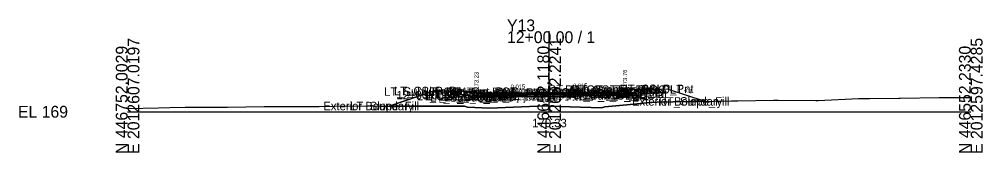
# Model space of a CAD drawing. Extents: x -26 to 1403, y -10 to 4517.
# Drawn here: x -25.7 to 202.8, y 3990.3 to 4021.9 of the extents above; entities that cross this region are included whole.
import ezdxf

# ---------------------------------------------------------------- set-up
doc = ezdxf.new("R2010")
doc.units = 0
for name, color, linetype in [('Default', 7, 'Continuous'), ('Exist Cross Section Cell', 7, 'Continuous'), ('Exist XS Center Line Elevation Label', 7, 'Continuous'), ('Exist XS Ground Line', 7, 'Continuous'), ('Prop CMT Conc Surface', 7, 'Continuous'), ('Prop CMT Concrete Structures', 7, 'Continuous'), ('Prop CMT Pvmt Course 1', 7, 'Continuous'), ('Prop CMT Pvmt Course 1 CG', 7, 'Continuous'), ('Prop CMT Pvmt Course 2', 7, 'Continuous'), ('Prop CMT Pvmt Course 3', 7, 'Continuous'), ('Prop CMT Pvmt Surface', 7, 'Continuous'), ('Prop CMT Slope Grass', 7, 'Continuous'), ('Prop CMT Subgrade Earthwork', 7, 'Continuous'), ('Prop XS Earthwork Shape', 7, 'Continuous'), ('Prop XS Hydro Elevations', 7, 'Continuous'), ('Prop XS SE Text', 7, 'Continuous'), ('Prop XS Side Slope Text', 7, 'Continuous'), ('Scratch_Level_0', 7, 'Continuous')]:
    doc.layers.add(name, color=color, linetype=linetype)

msp = doc.modelspace()

# ---------------------------------------------------------------- linework, layer by layer
at = {"layer": 'Exist Cross Section Cell'}
for p, q in [((100, 4000), (100, 4019.05)), ((0, 4000), (100, 4000)), ((100, 4000), (200, 4000))]:
    msp.add_line(p, q, dxfattribs=at)
at = {"layer": 'Exist XS Ground Line'}
msp.add_lwpolyline([(0, 4000.79), (7.31, 4000.95), (9.99, 4001.02), (13.63, 4001.09), (22.66, 4001.07), (23.71, 4001.07), (32.37, 4001.23), (40.65, 4001.21), (45.43, 4001.23), (52.89, 4001.42), (59.88, 4001.35), (72.72, 4001.32), (79.95, 4001.3), (80.65, 4001.12), (85.84, 4000.87), (99.11, 4001.38), (100, 4001.33), (112.41, 4000.89), (113.18, 4001.18), (118.45, 4001.64), (123.2, 4002.15), (125.62, 4002.24), (133.21, 4002.44), (135.17, 4002.45), (143.22, 4002.58), (144.72, 4002.58), (153.24, 4002.72), (154.28, 4002.72), (163.25, 4002.67), (163.83, 4002.7), (173.39, 4003.13), (175.98, 4003.16), (182.94, 4003.23), (183.27, 4003.24), (192.49, 4003.41), (193.29, 4003.41), (200, 4003.36)], dxfattribs=at)
at = {"layer": 'Prop CMT Conc Surface'}
for points in [[(82.75, 4004.23), (82.75, 4004.73), (82.25, 4004.73)], [(84.75, 4004.34), (82.75, 4004.23)], [(115.99, 4004.81), (117.99, 4004.76)], [(117.99, 4004.76), (118, 4005.26), (118.5, 4005.26)]]:
    msp.add_lwpolyline(points, dxfattribs=at)
at = {"layer": 'Prop CMT Concrete Structures'}
for points in [[(84.75, 4004.34), (82.75, 4004.23), (82.75, 4004.73), (82.25, 4004.73)], [(82.25, 4004.73), (82.25, 4003.72), (84.75, 4003.76)], [(84.75, 4003.76), (84.75, 4004.34)], [(115.99, 4004.81), (117.99, 4004.76), (118, 4005.26), (118.5, 4005.26)], [(118.5, 4005.26), (118.49, 4004.26), (115.99, 4004.23)], [(115.99, 4004.23), (115.99, 4004.81)]]:
    msp.add_lwpolyline(points, dxfattribs=at)
at = {"layer": 'Prop CMT Pvmt Course 1'}
for points in [[(100, 4004.57), (84.75, 4004.34)], [(84.75, 4004.34), (84.75, 4004.09)], [(84.75, 4004.09), (100, 4004.32)], [(100, 4004.57), (115.99, 4004.81)], [(100, 4004.32), (100, 4004.57)], [(100, 4004.32), (100, 4004.57)], [(115.99, 4004.56), (100, 4004.32)], [(115.99, 4004.81), (115.99, 4004.56)]]:
    msp.add_lwpolyline(points, dxfattribs=at)
msp.add_lwpolyline([(100, 4004.32), (100, 4004.44), (100, 4004.44), (100, 4004.32)], close=True, dxfattribs=at)
msp.add_lwpolyline([(100, 4004.32), (100, 4004.44), (100, 4004.44), (100, 4004.32)], close=True, dxfattribs=at)
at = {"layer": 'Prop CMT Pvmt Course 1 CG'}
for points in [[(115.99, 4004.23), (118.99, 4004.27), (119.32, 4003.94)], [(115.99, 4003.89), (115.99, 4004.23)], [(119.32, 4003.94), (115.99, 4003.89)], [(84.75, 4003.76), (81.75, 4003.71), (81.41, 4003.37)], [(81.41, 4003.37), (84.75, 4003.42)], [(84.75, 4003.42), (84.75, 4003.76)]]:
    msp.add_lwpolyline(points, dxfattribs=at)
at = {"layer": 'Prop CMT Pvmt Course 2'}
for points in [[(100, 4004.32), (84.75, 4004.09)], [(84.75, 4004.09), (84.75, 4003.76)], [(84.75, 4003.76), (100, 4003.99)], [(100, 4004.32), (115.99, 4004.56)], [(100, 4003.99), (100, 4004.32)], [(100, 4003.99), (100, 4004.32)], [(115.99, 4004.23), (100, 4003.99)], [(115.99, 4004.56), (115.99, 4004.23)]]:
    msp.add_lwpolyline(points, dxfattribs=at)
at = {"layer": 'Prop CMT Pvmt Course 3'}
for points in [[(100, 4003.99), (84.75, 4003.76)], [(100, 4003.99), (115.99, 4004.23)], [(100, 4003.65), (100, 4003.99)], [(100, 4003.65), (100, 4003.99)], [(115.99, 4003.89), (100, 4003.65)], [(115.99, 4004.23), (115.99, 4003.89)], [(84.75, 4003.76), (84.75, 4003.42)], [(84.75, 4003.42), (100, 4003.65)]]:
    msp.add_lwpolyline(points, dxfattribs=at)
at = {"layer": 'Prop CMT Pvmt Surface'}
for points in [[(100, 4004.57), (84.75, 4004.34)], [(100, 4004.57), (115.99, 4004.81)]]:
    msp.add_lwpolyline(points, dxfattribs=at)
at = {"layer": 'Prop CMT Slope Grass'}
for points in [[(82.25, 4004.73), (72.75, 4004.92), (62.03, 4001.35)], [(118.5, 4005.26), (128, 4005.45), (136.92, 4002.48)]]:
    msp.add_lwpolyline(points, dxfattribs=at)
at = {"layer": 'Prop CMT Subgrade Earthwork'}
for points in [[(84.75, 4003.42), (81.41, 4003.37), (80.01, 4004.77)], [(100, 4003.65), (115.99, 4003.89)], [(115.99, 4003.89), (119.32, 4003.94), (120.68, 4005.3)], [(100, 4003.65), (84.75, 4003.42)]]:
    msp.add_lwpolyline(points, dxfattribs=at)
at = {"layer": 'Prop XS Earthwork Shape'}
msp.add_lwpolyline([(115.99, 4003.89), (119.32, 4003.94), (120.68, 4005.3), (128, 4005.45), (136.92, 4002.48), (135.17, 4002.45), (133.21, 4002.44), (125.62, 4002.24), (123.2, 4002.15), (118.45, 4001.64), (113.18, 4001.18), (112.41, 4000.89), (100, 4001.33), (99.11, 4001.38), (85.84, 4000.87), (80.65, 4001.12), (79.95, 4001.3), (72.72, 4001.32), (62.03, 4001.35), (72.75, 4004.92), (80.01, 4004.77), (81.41, 4003.37), (84.75, 4003.42), (100, 4003.65)], close=True, dxfattribs=at)

# ---------------------------------------------------------------- texts
at = {"layer": 'Default'}
msp.add_text('-', height=0.0001, dxfattribs=at).set_placement((0, 4000))
at = {"layer": 'Exist Cross Section Cell'}
for s, p in [('Y13', (90, 4019.05)), ('12+00.00 / 1', (90, 4016.25)), ('EL 169', (-26, 3998.6))]:
    msp.add_text(s, height=2.8, dxfattribs=at).set_placement(p)
for s, p in [('N 446752.0029', (0, 3990)), ('E 2012607.0197', (2.8, 3990)), ('N 446652.1180', (100, 3990)), ('E 2012602.2241', (102.8, 3990)), ('N 446552.2330', (200, 3990)), ('E 2012597.4285', (202.8, 3990))]:
    msp.add_text(s, height=2.8, rotation=90, dxfattribs=at).set_placement(p)
at = {"layer": 'Exist XS Center Line Elevation Label'}
msp.add_text('170.33', height=2, dxfattribs=at).set_placement((95.99, 3996.33))
at = {"layer": 'Prop XS Hydro Elevations'}
for s, p in [('173.23', (83.25, 4005.23)), ('173.76', (118.49, 4005.76))]:
    msp.add_text(s, height=1, rotation=90, dxfattribs=at).set_placement(p)
at = {"layer": 'Prop XS SE Text'}
for p in [(90.88, 4005.43), (105.66, 4005.65)]:
    msp.add_text('0.015', height=1, rotation=0.8594, dxfattribs=at).set_placement(p)
at = {"layer": 'Prop XS Side Slope Text'}
for rotation, p in [(18.4332, (66.39, 4003.59)), (341.5668, (131.95, 4004.92))]:
    msp.add_text('3:1', height=1, rotation=rotation, dxfattribs=at).set_placement(p)
at = {"layer": 'Scratch_Level_0'}
for s, p in [('RT_Sub_Trench_Out_DLT', (99.79, 4004.28)), ('RT_CG_Top_Face', (103.79, 4004.24)), ('RT_CG_Top_BOC', (105.31, 4004.24)), ('RT_CSLP_Pnt', (116.7, 4004.43)), ('LT_Sub_Trench_Out_DLT', (60.84, 4003.78)), ('LT_CSLP_Pnt', (63.18, 4003.92)), ('12+00.00', (63.8, 4002.94)), ('LT_CG1_Shelf_Out', (68.56, 4002.72)), ('LT_CG_Top_Face', (70.27, 4003.73)), ('LT_CG_Top_BOC', (70.79, 4003.73)), ('LT_CG_Bot_BOC', (70.83, 4002.72)), ('LT_CG_Top_Gut', (71.25, 4003.23)), ('LT_Sub_OEOP', (71.78, 4002.38)), ('LT_CG_Bot_IE', (74.92, 4002.76)), ('LT_Sub_OEOT', (75.09, 4002.43)), ('LT_PV2_OEOT', (75.18, 4003.09)), ('LT_PV3_OEOT', (75.18, 4002.76)), ('LT_PV1_OEOT', (75.75, 4003.34)), ('RT_Sub_OEEOP', (89.17, 4002.65)), ('LT_Sub_OEEOP', (89.21, 4002.65)), ('RT_PV2_OEEOP', (89.26, 4003.32)), ('RT_PV3_OEEOP', (89.26, 4002.99)), ('LT_PV2_OEEOP', (89.31, 4003.32)), ('LT_PV3_OEEOP', (89.31, 4002.99)), ('RT_PV1_OEEOP', (89.83, 4003.44)), ('LT_PV1_OEEOP', (89.87, 4003.44)), ('RT_PV2_IEEOP', (89.91, 4003.32)), ('LT_PV2_IEEOP', (89.95, 4003.32)), ('RT_PV1_IEEOP', (90.47, 4003.44)), ('LT_PV1_IEEOP', (90.52, 4003.44)), ('PV2_PGL', (93.91, 4003.32)), ('PV1_PGL', (94.47, 4003.57)), ('RT_CG1_Shelf_Out', (104.08, 4003.25)), ('RT_CG_Bot_IE', (104.44, 4003.2)), ('RT_Sub_OEOT', (104.61, 4002.87)), ('RT_PV2_OEOT', (104.7, 4003.54)), ('RT_PV3_OEOT', (104.7, 4003.2)), ('RT_CG_Top_Gut', (104.77, 4003.74)), ('RT_PV1_OEOT', (105.27, 4003.79)), ('RT_CG_Bot_BOC', (105.34, 4003.24)), ('RT_Sub_OEOP', (107.97, 4002.92)), ('Exterior Boundary', (46.42, 4000.35)), ('LT_Slope_Fill', (52.8, 4000.35)), ('Exterior Boundary', (119.65, 4001.45)), ('RT_Slope_Fill', (125.98, 4001.45))]:
    msp.add_text(s, height=2, dxfattribs=at).set_placement(p)

doc.saveas('drawing.dxf')
